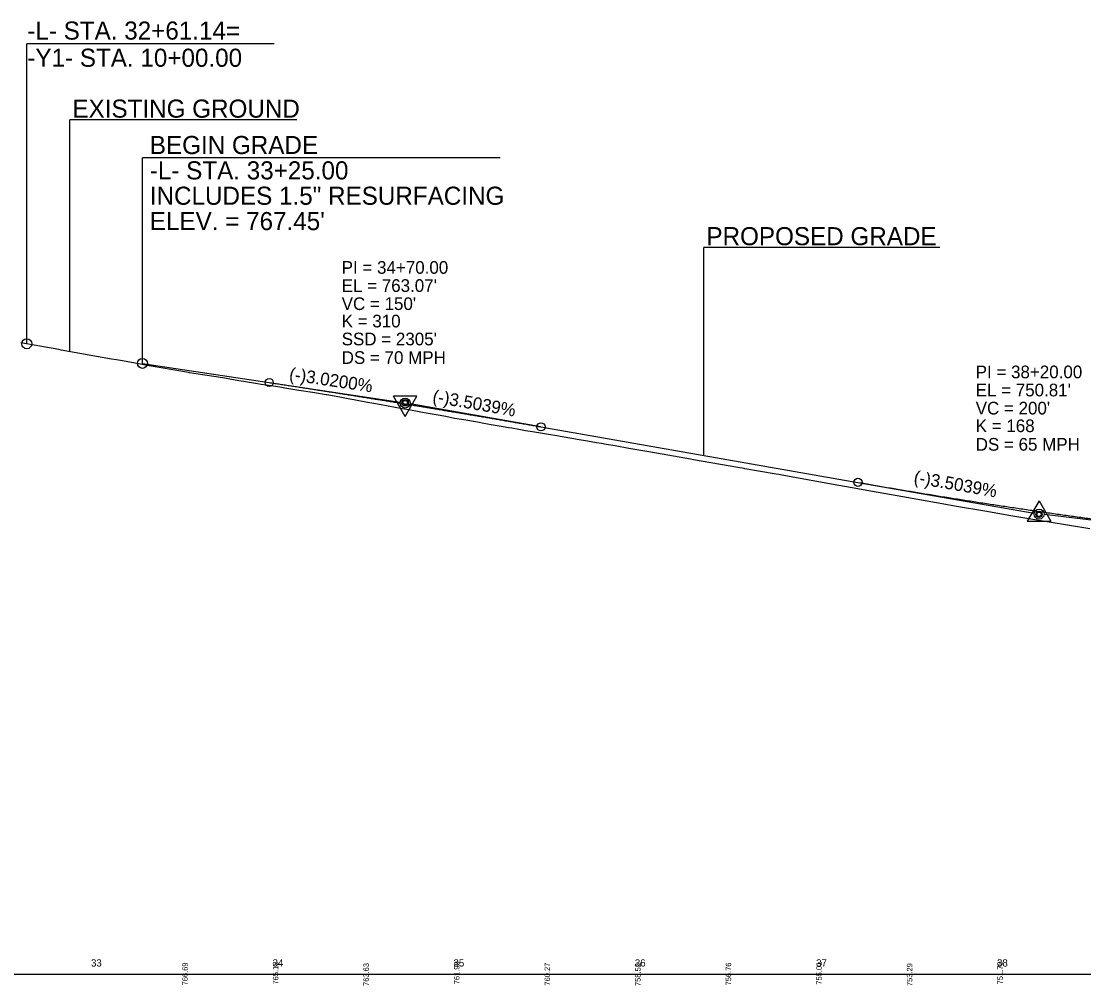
# Model space of a CAD drawing. Extents: x 1554255 to 1803987, y 659549 to 692876.
# Drawn here: x 1557052 to 1557638, y 692256 to 692788 of the extents above; entities that cross this region are included whole.
import ezdxf

# ---------------------------------------------------------------- set-up
doc = ezdxf.new("R2010")
doc.units = 0
for name, color, linetype in [('Default', 7, 'Continuous'), ('Exist Profile Cell', 7, 'Continuous'), ('Exist Vertical Profile Ground Line', 7, 'Continuous'), ('Prop PFL Text', 7, 'Continuous'), ('Prop PFL VPI Symbol CELL', 7, 'Continuous'), ('Prop Vertical Profile Curve Label', 7, 'Continuous'), ('Prop Vertical Profile Grade', 7, 'Continuous'), ('Prop Vertical Profile Grade Label', 7, 'Continuous'), ('Prop Vertical Profile Strip Grade', 7, 'Continuous'), ('Prop VPI Label', 7, 'Continuous')]:
    doc.layers.add(name, color=color, linetype=linetype)

msp = doc.modelspace()

# ---------------------------------------------------------------- linework, layer by layer
at = {"layer": 'Exist Profile Cell'}
msp.add_line((1554793.69, 692261.88), (1561762.5, 692261.88), dxfattribs=at)
at = {"layer": 'Exist Vertical Profile Ground Line'}
for p, q in [((1557072.46, 692606.72), (1557051.5, 692610.53)), ((1557073.9, 692606.46), (1557072.46, 692606.72)), ((1557101.52, 692601.52), (1557073.9, 692606.46)), ((1557104.33, 692601.01), (1557101.52, 692601.52)), ((1557106.65, 692600.67), (1557104.33, 692601.01)), ((1557113.79, 692599.39), (1557106.65, 692600.67)), ((1557120.43, 692598.21), (1557113.79, 692599.39)), ((1557121.39, 692598.04), (1557120.43, 692598.21)), ((1557128.98, 692596.7), (1557121.39, 692598.04)), ((1557135.56, 692595.54), (1557128.98, 692596.7)), ((1557136.58, 692595.37), (1557135.56, 692595.54)), ((1557144.18, 692594.06), (1557136.58, 692595.37)), ((1557144.62, 692593.98), (1557144.18, 692594.06)), ((1557151.77, 692592.83), (1557144.62, 692593.98)), ((1557159.37, 692591.62), (1557151.77, 692592.83)), ((1557165.06, 692590.7), (1557159.37, 692591.62)), ((1557166.96, 692590.37), (1557165.06, 692590.7)), ((1557171.87, 692589.52), (1557166.96, 692590.37)), ((1557174.56, 692589.09), (1557171.87, 692589.52)), ((1557182.16, 692587.86), (1557174.56, 692589.09)), ((1557184.23, 692587.52), (1557182.16, 692587.86)), ((1557189.75, 692586.65), (1557184.23, 692587.52)), ((1557194.54, 692585.9), (1557189.75, 692586.65)), ((1557197.35, 692585.45), (1557194.54, 692585.9)), ((1557204.95, 692584.22), (1557197.35, 692585.45)), ((1557212.54, 692582.99), (1557204.95, 692584.22)), ((1557213.63, 692582.81), (1557212.54, 692582.99)), ((1557220.14, 692581.79), (1557213.63, 692582.81)), ((1557220.5, 692581.73), (1557220.14, 692581.79)), ((1557227.74, 692580.42), (1557220.5, 692581.73)), ((1557233.14, 692579.44), (1557227.74, 692580.42)), ((1557235.33, 692579.03), (1557233.14, 692579.44)), ((1557242.93, 692577.61), (1557235.33, 692579.03)), ((1557245.24, 692577.18), (1557242.93, 692577.61)), ((1557250.52, 692576.22), (1557245.24, 692577.18)), ((1557258.12, 692574.84), (1557250.52, 692576.22)), ((1557262.13, 692574.11), (1557258.12, 692574.84)), ((1557265.72, 692573.44), (1557262.13, 692574.11)), ((1557271.49, 692572.35), (1557265.72, 692573.44)), ((1557273.31, 692572.01), (1557271.49, 692572.35)), ((1557275.31, 692571.62), (1557273.31, 692572.01)), ((1557280.91, 692570.63), (1557275.31, 692571.62)), ((1557286.16, 692569.71), (1557280.91, 692570.63)), ((1557288.51, 692569.25), (1557286.16, 692569.71)), ((1557291.04, 692568.76), (1557288.51, 692569.25)), ((1557296.1, 692567.89), (1557291.04, 692568.76)), ((1557303.7, 692566.59), (1557296.1, 692567.89)), ((1557307.08, 692566.01), (1557303.7, 692566.59)), ((1557311.29, 692565.27), (1557307.08, 692566.01)), ((1557318.89, 692563.93), (1557311.29, 692565.27)), ((1557320.78, 692563.59), (1557318.89, 692563.93)), ((1557322.64, 692563.27), (1557320.78, 692563.59)), ((1557326.49, 692562.6), (1557322.64, 692563.27)), ((1557330.11, 692561.96), (1557326.49, 692562.6)), ((1557334.08, 692561.29), (1557330.11, 692561.96)), ((1557341.68, 692560.02), (1557334.08, 692561.29)), ((1557348.6, 692558.87), (1557341.68, 692560.02)), ((1557349.28, 692558.75), (1557348.6, 692558.87)), ((1557356.87, 692557.41), (1557349.28, 692558.75)), ((1557358.62, 692557.1), (1557356.87, 692557.41)), ((1557364.47, 692556.13), (1557358.62, 692557.1)), ((1557369.42, 692555.3), (1557364.47, 692556.13)), ((1557372.07, 692554.85), (1557369.42, 692555.3)), ((1557374.77, 692554.39), (1557372.07, 692554.85)), ((1557379.66, 692553.54), (1557374.77, 692554.39)), ((1557387.26, 692552.21), (1557379.66, 692553.54)), ((1557394.85, 692550.88), (1557387.26, 692552.21)), ((1557397.11, 692550.48), (1557394.85, 692550.88)), ((1557402.52, 692549.56), (1557397.11, 692550.48)), ((1557421.29, 692546.26), (1557402.52, 692549.56)), ((1557422.98, 692545.96), (1557421.29, 692546.26)), ((1557447.43, 692541.68), (1557422.98, 692545.96)), ((1557450.93, 692541.06), (1557447.43, 692541.68)), ((1557451.33, 692540.99), (1557450.93, 692541.06)), ((1557468.6, 692537.94), (1557451.33, 692540.99)), ((1557470.01, 692537.7), (1557468.6, 692537.94)), ((1557472.71, 692537.21), (1557470.01, 692537.7)), ((1557500, 692532.32), (1557472.71, 692537.21)), ((1557513.61, 692529.88), (1557500, 692532.32)), ((1557518.62, 692528.99), (1557513.61, 692529.88)), ((1557538.41, 692525.39), (1557518.62, 692528.99)), ((1557548.69, 692523.61), (1557538.41, 692525.39)), ((1557560.16, 692521.54), (1557548.69, 692523.61)), ((1557568.11, 692520.16), (1557560.16, 692521.54)), ((1557583.68, 692517.46), (1557568.11, 692520.16)), ((1557598.13, 692515.01), (1557583.68, 692517.46)), ((1557611.42, 692512.7), (1557598.13, 692515.01)), ((1557619.17, 692511.38), (1557611.42, 692512.7)), ((1557641.64, 692507.84), (1557619.17, 692511.38))]:
    msp.add_line(p, q, dxfattribs=at)
at = {"layer": 'Prop PFL Text'}
for p, q in [((1557054.83, 692609.93), (1557054.83, 692775.58)), ((1557191.35, 692775.58), (1557054.83, 692775.58)), ((1557078.69, 692605.61), (1557078.69, 692733.55)), ((1557203.99, 692733.55), (1557078.69, 692733.55)), ((1557316.24, 692712.56), (1557118.69, 692712.56)), ((1557118.69, 692599.13), (1557118.69, 692712.56)), ((1557428.69, 692548.13), (1557428.69, 692663.13)), ((1557558.82, 692663.13), (1557428.69, 692663.13))]:
    msp.add_line(p, q, dxfattribs=at)
at = {"layer": 'Prop PFL VPI Symbol CELL'}
for p, q in [((1557263.74, 692569.88), (1557257.24, 692581.08)), ((1557270.19, 692581.08), (1557257.24, 692581.08)), ((1557263.74, 692569.88), (1557270.19, 692581.08)), ((1557613.64, 692523.26), (1557607.19, 692512.06)), ((1557613.64, 692523.26), (1557620.14, 692512.06)), ((1557607.19, 692512.06), (1557620.14, 692512.06))]:
    msp.add_line(p, q, dxfattribs=at)
for centre, radius in [((1557263.73, 692577.36), 1.75), ((1557263.73, 692577.36), 1.2), ((1557613.65, 692515.78), 1.75), ((1557613.65, 692515.78), 1.2)]:
    msp.add_circle(centre, radius, dxfattribs=at)
at = {"layer": 'Prop Vertical Profile Curve Label'}
for centre in [(1557188.69, 692588.56), (1557338.69, 692564.09), (1557513.69, 692533.43)]:
    msp.add_circle(centre, 2.25, dxfattribs=at)
at = {"layer": 'Prop Vertical Profile Grade'}
for p, q in [((1557118.69, 692599.13), (1557188.69, 692588.56)), ((1557338.69, 692564.09), (1557513.69, 692533.43))]:
    msp.add_line(p, q, dxfattribs=at)
for points in [[(1557188.69, 692588.56), (1557191.69, 692588.1), (1557194.69, 692587.65), (1557197.69, 692587.19), (1557200.69, 692586.73), (1557203.69, 692586.27), (1557206.69, 692585.81), (1557209.69, 692585.35), (1557212.69, 692584.89), (1557215.69, 692584.42), (1557218.69, 692583.95), (1557221.69, 692583.49), (1557224.69, 692583.02), (1557227.69, 692582.55), (1557230.69, 692582.07), (1557233.69, 692581.6), (1557236.69, 692581.12), (1557239.69, 692580.65), (1557242.69, 692580.17), (1557245.69, 692579.69), (1557248.69, 692579.21), (1557251.69, 692578.72), (1557254.69, 692578.24), (1557257.69, 692577.75), (1557260.69, 692577.27), (1557263.69, 692576.78), (1557266.69, 692576.29), (1557269.69, 692575.8), (1557272.69, 692575.3), (1557275.69, 692574.81), (1557278.69, 692574.31), (1557281.69, 692573.82), (1557284.69, 692573.32), (1557287.69, 692572.82), (1557290.69, 692572.32), (1557293.69, 692571.81), (1557296.69, 692571.31), (1557299.69, 692570.8), (1557302.69, 692570.3), (1557305.69, 692569.79), (1557308.69, 692569.28), (1557311.69, 692568.76), (1557314.69, 692568.25), (1557317.69, 692567.74), (1557320.69, 692567.22), (1557323.69, 692566.7), (1557326.69, 692566.18), (1557329.69, 692565.66), (1557332.69, 692565.14), (1557335.69, 692564.62), (1557338.69, 692564.09)], [(1557513.69, 692533.43), (1557517.69, 692532.74), (1557521.69, 692532.04), (1557525.69, 692531.35), (1557529.69, 692530.67), (1557533.69, 692529.99), (1557537.69, 692529.32), (1557541.69, 692528.65), (1557545.69, 692527.98), (1557549.69, 692527.32), (1557553.69, 692526.67), (1557557.69, 692526.01), (1557561.69, 692525.37), (1557565.69, 692524.73), (1557569.69, 692524.09), (1557573.69, 692523.46), (1557577.69, 692522.83), (1557581.69, 692522.21), (1557585.69, 692521.59), (1557589.69, 692520.98), (1557593.69, 692520.37), (1557597.69, 692519.77), (1557601.69, 692519.17), (1557605.69, 692518.58), (1557609.69, 692517.99), (1557613.69, 692517.41), (1557617.69, 692516.83), (1557621.69, 692516.25), (1557625.69, 692515.68), (1557629.69, 692515.12), (1557633.69, 692514.56), (1557637.69, 692514), (1557641.69, 692513.45), (1557645.69, 692512.91), (1557649.69, 692512.37), (1557653.69, 692511.83), (1557657.69, 692511.3), (1557661.69, 692510.77), (1557665.69, 692510.25), (1557669.69, 692509.74), (1557673.69, 692509.22), (1557677.69, 692508.72), (1557681.69, 692508.21), (1557685.69, 692507.72), (1557689.69, 692507.22), (1557693.69, 692506.73), (1557697.69, 692506.25), (1557701.69, 692505.77), (1557705.69, 692505.3), (1557709.69, 692504.83), (1557713.69, 692504.36)]]:
    msp.add_spline(points, degree=3, dxfattribs=at)
at = {"layer": 'Prop VPI Label'}
for p, q in [((1557188.69, 692588.56), (1557260.97, 692577.64)), ((1557338.69, 692564.09), (1557266.4, 692576.76)), ((1557513.69, 692533.43), (1557610.98, 692516.39)), ((1557713.69, 692504.36), (1557616.42, 692515.6))]:
    msp.add_line(p, q, dxfattribs=at)
for centre in [(1557054.83, 692609.93), (1557118.69, 692599.13), (1557263.69, 692577.23), (1557613.69, 692515.91)]:
    msp.add_circle(centre, 2.75, dxfattribs=at)

# ---------------------------------------------------------------- texts
at = {"layer": 'Default'}
for s, p in [('33', (1557090.3, 692266.13)), ('34', (1557190.51, 692266.13)), ('35', (1557290.4, 692266.13)), ('36', (1557390.51, 692266.13)), ('37', (1557490.6, 692266.13)), ('38', (1557590.46, 692266.13))]:
    msp.add_text(s, height=4, dxfattribs=at).set_placement(p)
at = {"layer": 'Prop PFL Text'}
for s, p in [('-L- STA. 32+61.14=', (1557055.15, 692777.86)), ('-Y1- STA. 10+00.00', (1557055.15, 692762.86)), ('EXISTING GROUND', (1557080.03, 692734.77)), ('BEGIN GRADE', (1557122.77, 692714.68)), ('-L- STA. 33+25.00', (1557122.77, 692700.68)), ('INCLUDES 1.5" RESURFACING', (1557122.77, 692686.68)), ("ELEV. = 767.45'", (1557122.77, 692672.68)), ('PROPOSED GRADE', (1557430.03, 692664.35))]:
    msp.add_text(s, height=10, rotation=360, dxfattribs=at).set_placement(p)
at = {"layer": 'Prop Vertical Profile Curve Label'}
for s, p in [("VC = 150'", (1557228.69, 692628.58)), ('K = 310', (1557228.69, 692618.99)), ("SSD = 2305'", (1557228.69, 692609.08)), ('DS = 70 MPH', (1557228.69, 692598.84)), ("VC = 200'", (1557578.69, 692570.91)), ('K = 168', (1557578.69, 692561.17)), ('DS = 65 MPH', (1557578.69, 692550.92))]:
    msp.add_text(s, height=7, dxfattribs=at).set_placement(p)
at = {"layer": 'Prop Vertical Profile Grade Label'}
for s, rotation, p in [('(-)3.0200%', 351.41321, (1557199.41, 692589.97)), ('(-)3.5039%', 350.06303, (1557278.47, 692577.69)), ('(-)3.5039%', 350.06303, (1557544.15, 692533.08))]:
    msp.add_text(s, height=7, rotation=rotation, dxfattribs=at).set_placement(p)
at = {"layer": 'Prop Vertical Profile Strip Grade'}
for s, p in [('766.69', (1557143.69, 692255.71)), ('765.18', (1557193.69, 692256.2)), ('763.63', (1557243.69, 692255.39)), ('761.99', (1557293.69, 692256.33)), ('760.27', (1557343.69, 692255.59)), ('758.52', (1557393.69, 692255.35)), ('756.76', (1557443.69, 692255.69)), ('755.01', (1557493.69, 692256.09)), ('753.29', (1557543.69, 692255.31)), ('751.70', (1557593.69, 692256.26))]:
    msp.add_text(s, height=3, rotation=90, dxfattribs=at).set_placement(p)
at = {"layer": 'Prop VPI Label'}
for s, p in [('PI = 34+70.00', (1557228.69, 692648.58)), ("EL = 763.07'", (1557228.69, 692638.58)), ('PI = 38+20.00', (1557578.69, 692590.91)), ("EL = 750.81'", (1557578.69, 692580.91))]:
    msp.add_text(s, height=7, dxfattribs=at).set_placement(p)

doc.saveas('drawing.dxf')
